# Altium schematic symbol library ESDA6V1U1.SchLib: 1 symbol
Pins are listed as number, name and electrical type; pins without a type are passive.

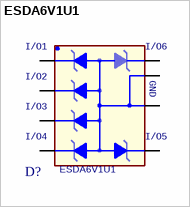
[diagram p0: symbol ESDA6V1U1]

## ESDA6V1U1
designator D?
footprint ST_SO8
pins: 1 I/O1, 2 I/O2, 3 I/O3, 4 I/O4, 5 I/O5, 6 GND, 7 GND1, 8 I/O6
